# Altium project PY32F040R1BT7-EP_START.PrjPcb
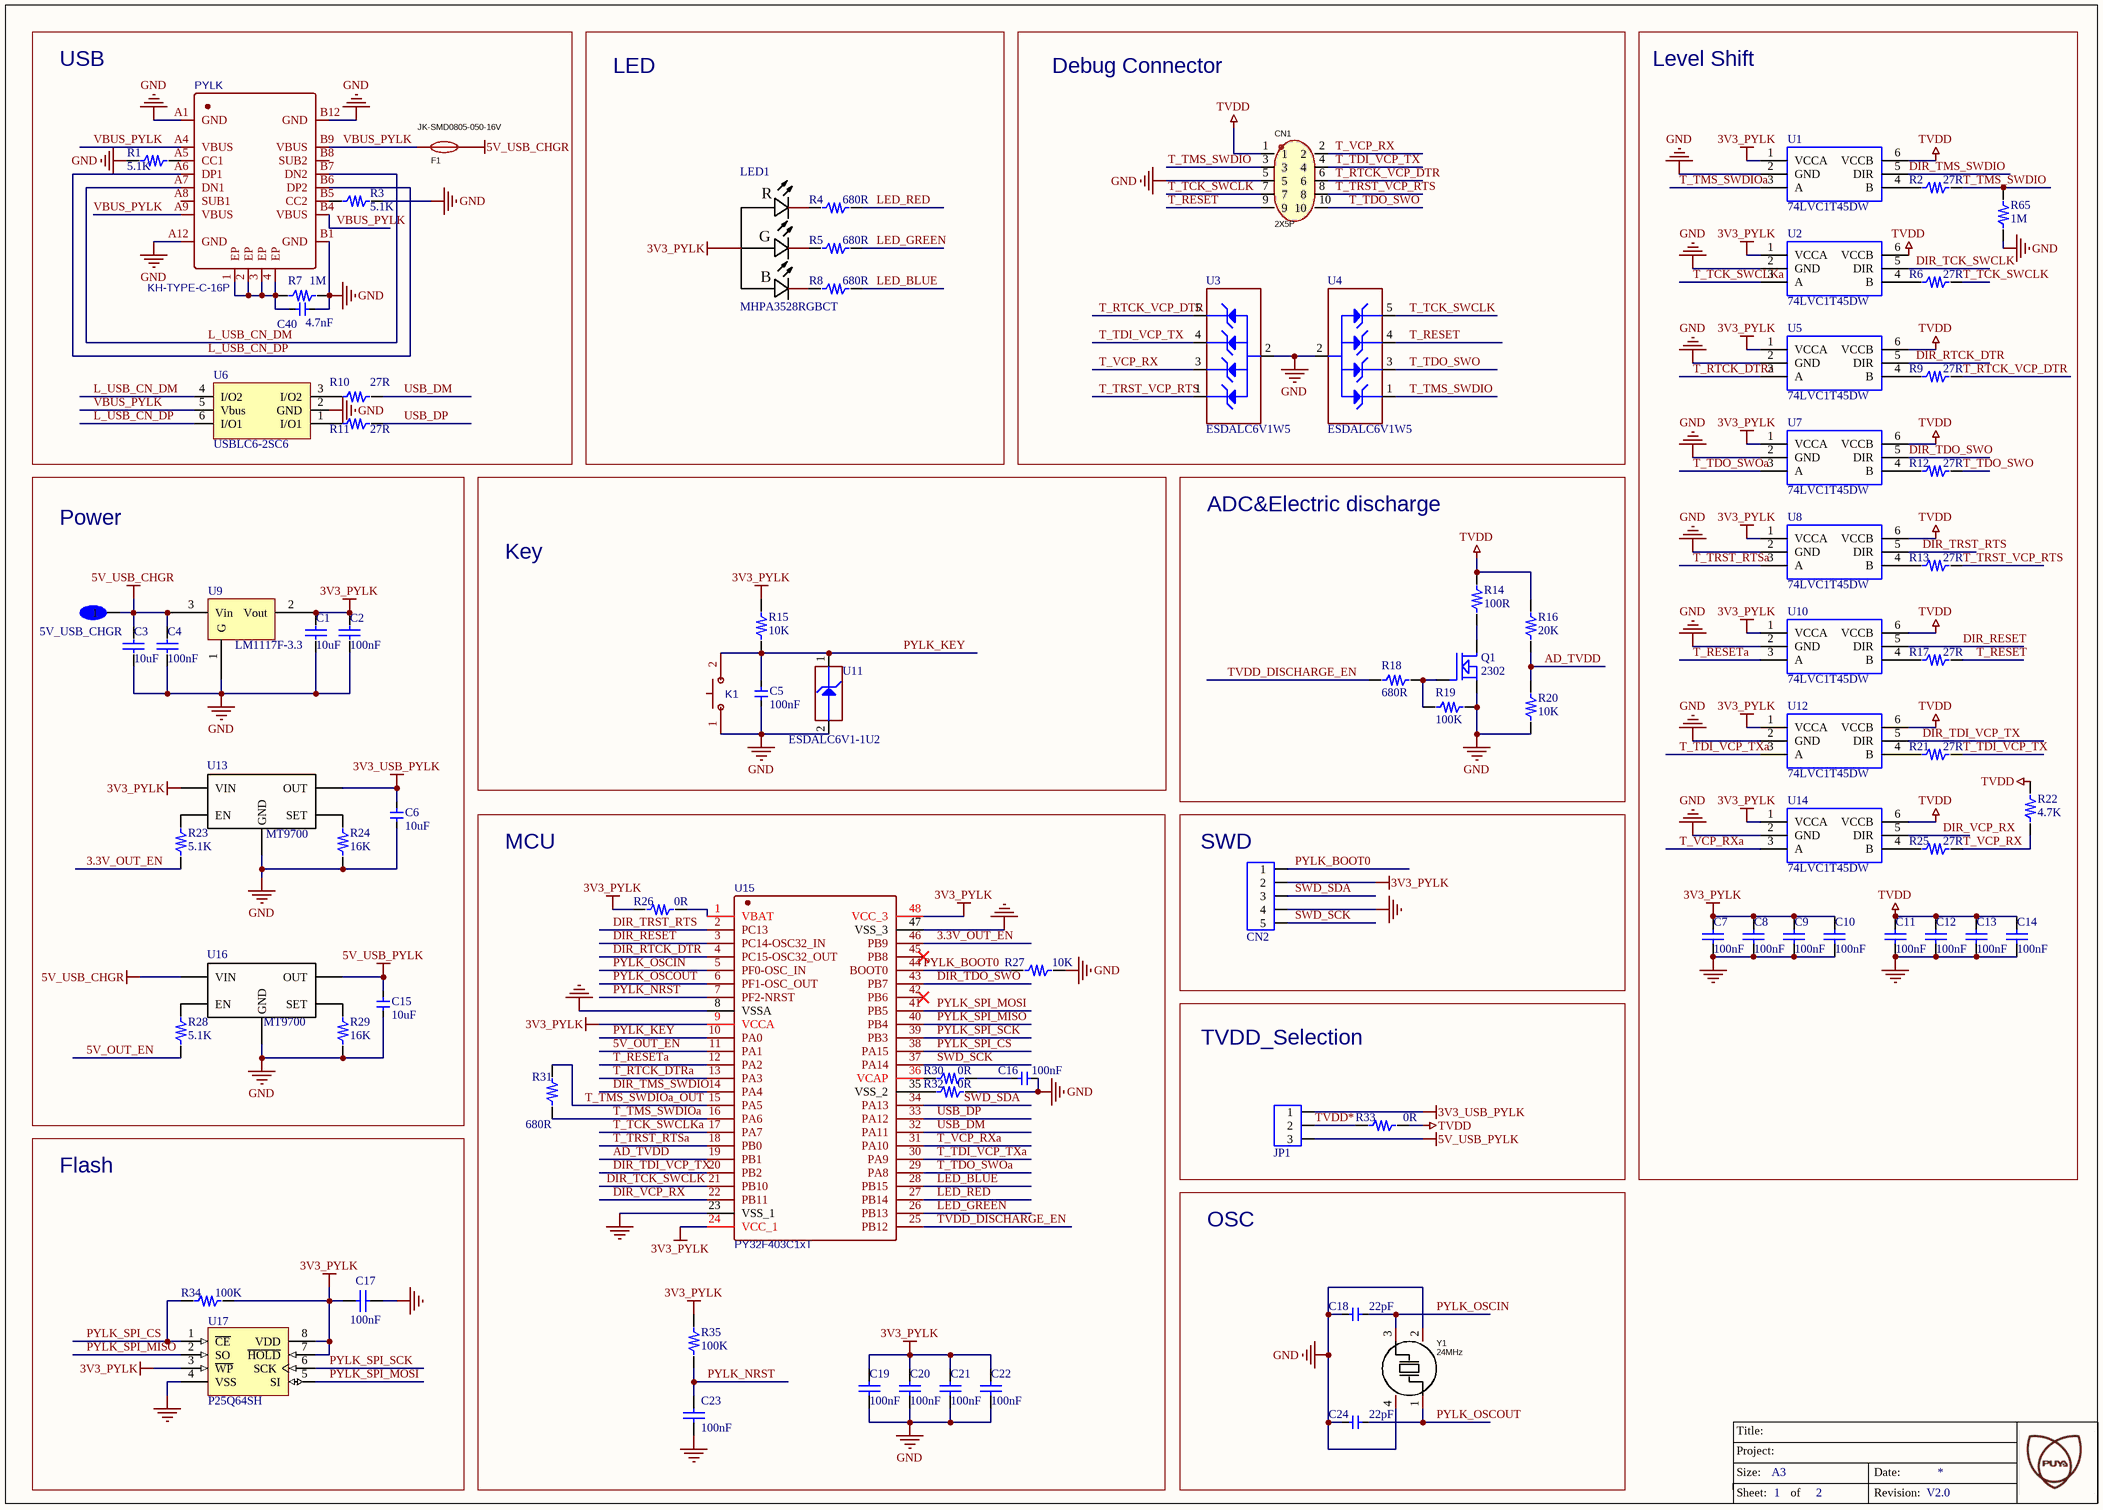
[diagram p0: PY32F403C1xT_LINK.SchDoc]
2 sheets, 157 parts. Net scope: global (net labels, ports and power ports of the same name join across sheets).
Board file: PY32F040R1BT7-EP_START.PcbDoc
Sheets:
  PY32F403C1xT_LINK.SchDoc
  PY32F040R1BT7-EP_START.SchDoc

## Sheet PY32F403C1xT_LINK.SchDoc: =DocumentName
size A3; Revision: V2.0; SheetNumber: 1; SheetTotal: 2; Project: PY32F040R1BT7-EP_START.PrjPcb

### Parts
5V_USB_CHGR  5V_USB_CHGR  [TP_SIN]
C1  10uF  [C0805]
C2  100nF  [C0603]
C3  10uF  [C0805]
C4  100nF  [C0603]
C5  100nF  [C0603]
C6  10uF  [C0805]
C7  100nF  [C0603]
C8  100nF  [C0603]
C9  100nF  [C0603]
C10  100nF  [C0603]
C11  100nF  [C0603]
C12  100nF  [C0603]
C13  100nF  [C0603]
C14  100nF  [C0603]
C15  10uF  [C0805]
C16  100nF  [C0603]
C17  100nF  [C0603]
C18  22pF  [C0603]
C19  100nF  [C0603]
C20  100nF  [C0603]
C21  100nF  [C0603]
C22  100nF  [C0603]
C23  100nF  [C0603]
C24  22pF  [C0603]
C40  4.7nF  [C0603]
CN1  2X5P  [HDR2X5]
CN2  CON5  [CON5]  (value not drawn)
F1  JK-SMD0805-050-16V  [F0805]
JP1  CON3  [CON3]  (value not drawn)
K1  TS-KG02S-AT43F  [Switch]  (value not drawn)
LED1  MHPA3528RGBCT  [LED-ARRAY-SMD_4P-L3.5-W2.8-TL]
PYLK  KH-TYPE-C-16P  [USB-C-SMD_KH-TYPE-C-16P]
Q1  2302  [SOT23]
R1  5.1K  [R0603]
R2  27R  [R0603]
R3  5.1K  [R0603]
R4  680R  [R0603]
R5  680R  [R0603]
R6  27R  [R0603]
R7  1M  [R0603]
R8  680R  [R0603]
R9  27R  [R0603]
R10  27R  [R0603]
R11  27R  [R0603]
R12  27R  [R0603]
R13  27R  [R0603]
R14  100R  [R0805]
R15  10K  [R0603]
R16  20K  [R0603]
R17  27R  [R0603]
R18  680R  [R0603]
R19  100K  [R0603]
R20  10K  [R0603]
R21  27R  [R0603]
R22  4.7K  [R0603]
R23  5.1K  [R0603]
R24  16K  [R0603]
R25  27R  [R0603]
R26  0R  [JP2_SMD]
R27  10K  [R0603]
R28  5.1K  [R0603]
R29  16K  [R0603]
R30  0R  [JP2_SMD]
R31  680R  [R0603]
R32  0R  [JP2_SMD]
R33  0R  [JP2_SMD]
R34  100K  [R0603]
R35  100K  [R0603]
R65  1M  [R0603]
U1  74LVC1T45DW  [SOT363]
U2  74LVC1T45DW  [SOT363]
U3  ESDALC6V1W5  [ESD_SOT323-5L]
U4  ESDALC6V1W5  [ESD_SOT323-5L]
U5  74LVC1T45DW  [SOT363]
U6  USBLC6-2SC6  [SOT23-6]
U7  74LVC1T45DW  [SOT363]
U8  74LVC1T45DW  [SOT363]
U9  LM1117F-3.3  [LM1117-3.3]
U10  74LVC1T45DW  [SOT363]
U11  value ESDALC6V1-1U2  [ESD_ST0201]  (hidden comment: ESD-TRANSIL)
U12  74LVC1T45DW  [SOT363]
U13  MT9700  [SOT23-5]
U14  74LVC1T45DW  [SOT363]
U15  PY32F403C1xT  [LQFP-48_L7.0-W7.0-P0.50-LS9.0-BL]
U16  MT9700  [SOT23-5]
U17  P25Q64SH  [SOP-8P]
Y1  24MHz  [CRYSTAL-SMD_4P-L3.2-W2.5-BL]

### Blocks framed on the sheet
USB: C40 F1 PYLK R1 R3 R7 R10 R11 U6
LED: LED1 R4 R5 R8
Debug Connector: CN1 U3 U4
Level Shift: C7-C14 R2 R6 R9 R12 R13 R17 R21 R22 R25 R65 U1 U2 U5 U7 U8 U10 U12 U14
Power: 5V_USB_CHGR C1-C4 C6 C15 R23 R24 R28 R29 U9 U13 U16
Key: C5 K1 R15 U11
ADC&Electric discharge: Q1 R14 R16 R18-R20
MCU: C16 C19-C23 R26 R27 R30-R32 R35 U15
SWD: CN2
TVDD_Selection: JP1 R33
Flash: C17 R34 U17
OSC: C18 C24 Y1

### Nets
3V3_PYLK: C1.2 C2.2 C7.2 C8.2 C9.2 C10.2 C17.2 C19.2 C20.2 C21.2 C22.2 CN2.2 LED1.1(-) R15.2 R26.1 R34.2 R35.2 U1.1(VCCA) U2.1(VCCA) U5.1(VCCA) U7.1(VCCA) U8.1(VCCA) U9.2(Vout) U10.1(VCCA) U12.1(VCCA) U13.5(VIN) U14.1(VCCA) U15.9(VCCA) U15.24(VCC_1) U15.48(VCC_3) U17.3(~{WP}) U17.7(~{HOLD}) U17.8(VDD)
3V3_USB_PYLK: C6.2 JP1.1 U13.1(OUT)
5V_USB_CHGR: 5V_USB_CHGR.1 C3.2 C4.2 F1.2 U9.3(Vin) U16.5(VIN)
5V_USB_PYLK: C15.2 JP1.3 U16.1(OUT)
GND: C1.1 C2.1 C3.1 C4.1 C5.1 C6.1 C7.1 C8.1 C9.1 C10.1 C11.1 C12.1 C13.1 C14.1 C15.1 C16.1 C17.1 C18.1 C19.1 C20.1 C21.1 C22.1 C23.1 C24.1 C40.1 CN1.5 CN2.4 K1.1(A) PYLK.A1(GND) PYLK.A12(GND) PYLK.B1(GND) PYLK.B12(GND) Q1.2(S) R1.1 R3.2 R7.2 R19.1 R20.1 R24.1 R27.2 R29.1 R32.2 R65.1 U1.2(GND) U2.2(GND) U3.2(GND) U4.2(GND) U5.2(GND) U6.2(GND) U7.2(GND) U8.2(GND) U9.1(G) U10.2(GND) U11.2(GND) U12.2(GND) U13.2(GND) U14.2(GND) U15.8(VSSA) U15.23(VSS_1) U15.47(VSS_3) U16.2(GND) U17.4(VSS) Y1.2(GND) Y1.4(GND)
TVDD: C11.2 C12.2 C13.2 C14.2 CN1.1 R14.2 R16.2 R22.2 R33.2 U1.6(VCCB) U2.6(VCCB) U5.6(VCCB) U7.6(VCCB) U8.6(VCCB) U10.6(VCCB) U12.6(VCCB) U14.6(VCCB)
3.3V_OUT_EN: R23.1 U15.46(PB9)
5V_OUT_EN: R28.1 U15.11(PA1)
AD_TVDD: R16.1 R20.2 U15.19(PB1)
DIR_RESET: U10.5(DIR) U15.3(PC14-OSC32_IN)
DIR_RTCK_DTR: U5.5(DIR) U15.4(PC15-OSC32_OUT)
DIR_TCK_SWCLK: U2.5(DIR) U15.21(PB10)
DIR_TDI_VCP_TX: U12.5(DIR) U15.20(PB2)
DIR_TDO_SWO: U7.5(DIR) U15.43(PB7)
DIR_TMS_SWDIO: U1.5(DIR) U15.14(PA4)
DIR_TRST_RTS: U8.5(DIR) U15.2(PC13)
DIR_VCP_RX: U14.5(DIR) U15.22(PB11)
L_USB_CN_DM: PYLK.A7(DN1) PYLK.B7(DN2) U6.4(I/O2)
L_USB_CN_DP: PYLK.A6(DP1) PYLK.B6(DP2) U6.6(I/O1)
LED_BLUE: R8.2 U15.28(PB15)
LED_GREEN: R5.2 U15.26(PB13)
LED_RED: R4.2 U15.27(PB14)
PYLK_BOOT0: CN2.1 R27.1 U15.44(BOOT0)
PYLK_KEY: C5.2 K1.2(B) R15.1 U11.1(IO1) U15.10(PA0)
PYLK_NRST: C23.2 R35.1 U15.7(PF2-NRST)
PYLK_OSCIN: C18.2 U15.5(PF0-OSC_IN) Y1.3(OSC2)
PYLK_OSCOUT: C24.2 U15.6(PF1-OSC_OUT) Y1.1(OSC1)
PYLK_SPI_CS: R34.1 U15.38(PA15) U17.1(~{CE})
PYLK_SPI_MISO: U15.40(PB4) U17.2(SO)
PYLK_SPI_MOSI: U15.41(PB5) U17.5(SI)
PYLK_SPI_SCK: U15.39(PB3) U17.6(SCK)
SWD_SCK: CN2.5 U15.37(PA14)
SWD_SDA: CN2.3 U15.34(PA13)
T_RESET: CN1.9 R17.2 U4.4(IO3)
T_RESETa: U10.3(A) U15.12(PA2)
T_RTCK_DTRa: U5.3(A) U15.13(PA3)
T_RTCK_VCP_DTR: CN1.6 R9.2 U3.5(IO4)
T_TCK_SWCLK: CN1.7 R6.2 U4.5(IO4)
T_TCK_SWCLKa: U2.3(A) U15.17(PA7)
T_TDI_VCP_TX: CN1.4 R21.2 U3.4(IO3)
T_TDI_VCP_TXa: U12.3(A) U15.30(PA9)
T_TDO_SWO: CN1.10 R12.2 U4.3(IO2)
T_TDO_SWOa: U7.3(A) U15.29(PA8)
T_TMS_SWDIO: CN1.3 R2.2 R65.2 U4.1(IO1)
T_TMS_SWDIOa: R31.1 U1.3(A) U15.16(PA6)
T_TMS_SWDIOa_OUT: R31.2 U15.15(PA5)
T_TRST_RTSa: U8.3(A) U15.18(PB0)
T_TRST_VCP_RTS: CN1.8 R13.2 U3.1(IO1)
T_VCP_RX: CN1.2 R22.1 R25.2 U3.3(IO2)
T_VCP_RXa: U14.3(A) U15.31(PA10)
TVDD*: JP1.2 R33.1
TVDD_DISCHARGE_EN: R18.2 U15.25(PB12)
USB_DM: R10.2 U15.32(PA11)
USB_DP: R11.2 U15.33(PA12)
VBUS_PYLK: F1.1 PYLK.A4(VBUS) PYLK.A9(VBUS) PYLK.B4(VBUS) PYLK.B9(VBUS) U6.5(Vbus)
NetC16_2: C16.2 R30.2
NetC40_2: C40.2 PYLK.1(EP) PYLK.2(EP) PYLK.3(EP) PYLK.4(EP) R7.1
NetLED1_2: LED1.2(-) R8.1
NetLED1_3: LED1.3(-) R5.1
NetLED1_4: LED1.4(-) R4.1
NetPYLK_A5: PYLK.A5(CC1) R1.2
NetPYLK_B5: PYLK.B5(CC2) R3.1
NetQ1_1: Q1.1(G) R18.1 R19.2
NetQ1_3: Q1.3(D) R14.1
NetR2_1: R2.1 U1.4(B)
NetR6_1: R6.1 U2.4(B)
NetR9_1: R9.1 U5.4(B)
NetR10_1: R10.1 U6.3(I/O2)
NetR11_1: R11.1 U6.1(I/O1)
NetR12_1: R12.1 U7.4(B)
NetR13_1: R13.1 U8.4(B)
NetR17_1: R17.1 U10.4(B)
NetR21_1: R21.1 U12.4(B)
NetR23_2: R23.2 U13.4(EN)
NetR24_2: R24.2 U13.3(SET)
NetR25_1: R25.1 U14.4(B)
NetR26_2: R26.2 U15.1(VBAT)
NetR28_2: R28.2 U16.4(EN)
NetR29_2: R29.2 U16.3(SET)
NetR30_1: R30.1 U15.36(VCAP)
NetR32_1: R32.1 U15.35(VSS_2)

Not connected (* = marked no-connect by the designer): PYLK A8(SUB1) B8(SUB2); U15 42(PB6)* 45(PB8)*

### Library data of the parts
5V_USB_CHGR = TP_SIN
C1 C3 C6 C15 = C0805: PCB DECAL: 0805
C2 C4 C5 C16 C18 C24 C40 = C0603: PCB DECAL: 0603
C7-C14 C17 C19-C23 = 贴片高压陶瓷电容: Capacitor (Semiconductor SIM Model); 器件封装(外观): 0603; Value: 104
CN1 = 2X5P: Manufacturer: XFCN(兴飞); Symbol: PZ254V-12-10P; Add into BOM: yes; Pitch: 2.54mm; Circluar Pins/Square Pins: 方针
F1 = JK-SMD0805-050-16V: Manufacturer: JK(金科); Add into BOM: yes; Voltage - Max: 6V; Current - Max: 100A; Hold Current: 500mA; Trip Current: 1A; Power Dissipation: 600mW; Resistance - Initial (Ri) (Min): 150mΩ; Resistance - Post Trip (R1) (Max): 850mΩ; Time to Trip(Max): 100ms
K1 = 1TS002B-2600-5001_key: BOM_Manufacturer: HYP; Contributor: LCSC
LED1 = MHPA3528RGBCT: Manufacturer: MEIHUA(美华); Add into BOM: yes
PYLK = KH-TYPE-C-16P: BOM_Manufacturer: Shenzhen Kinghelm Elec; Contributor: LCSC
Q1 = MOSFET N: Value: SI2302
R1-R13 R15-R35 R65 = R0603: PCB DECAL: 0603
R14 = R0805: PCB DECAL: 0805
U3 U4 = ESDALC6V1W5: Dual Transil array for ESD protection; Internal_Part_Number: MCD-00136; Part_Type: Diode; Manufacturer: STMICROELECTRONICS; ECCN_US: EAR99; ECCN_EU: NEC; Provided_By: Subcon; Initial_Board_Reference: MB1262
U6 = USBLC6-2SC6: Function: ESD EMI fliter
U9 = LM1117-3.3
U11 = ESD-TRANSIL: ESD protection 6V1; Internal_Part_Number: MCD-00170; Part_Type: Diode; Manufacturer: STMICROELECTRONICS; ECCN_US: EAR99; ECCN_EU: NEC; Provided_By: Subcon; Initial_Board_Reference: MB1274
U15 = PY32F403C1xT: LQFP48; BOM_Manufacturer: PUYA(普冉)
U17 = SST25VF010: Value: SST25VF020B; 器件封装(外观): SOP8
Y1 = ABM8AIG-24.000MHZ-82Z-T: ±20ppm , 12.5pF , T_use: -40°C~125°C; Manufacturer: ABRACON; Add into BOM: yes; External load capacitor: 8pF; Frequency Stability(Full temperature range): ±50ppm; Equivalent Series Resistance (ESR): 50Ω

## Sheet PY32F040R1BT7-EP_START.SchDoc: =DocumentName
size A3; Revision: V2.0; SheetNumber: 2; SheetTotal: 2; Project: PY32F040R1BT7-EP_START.PrjPcb
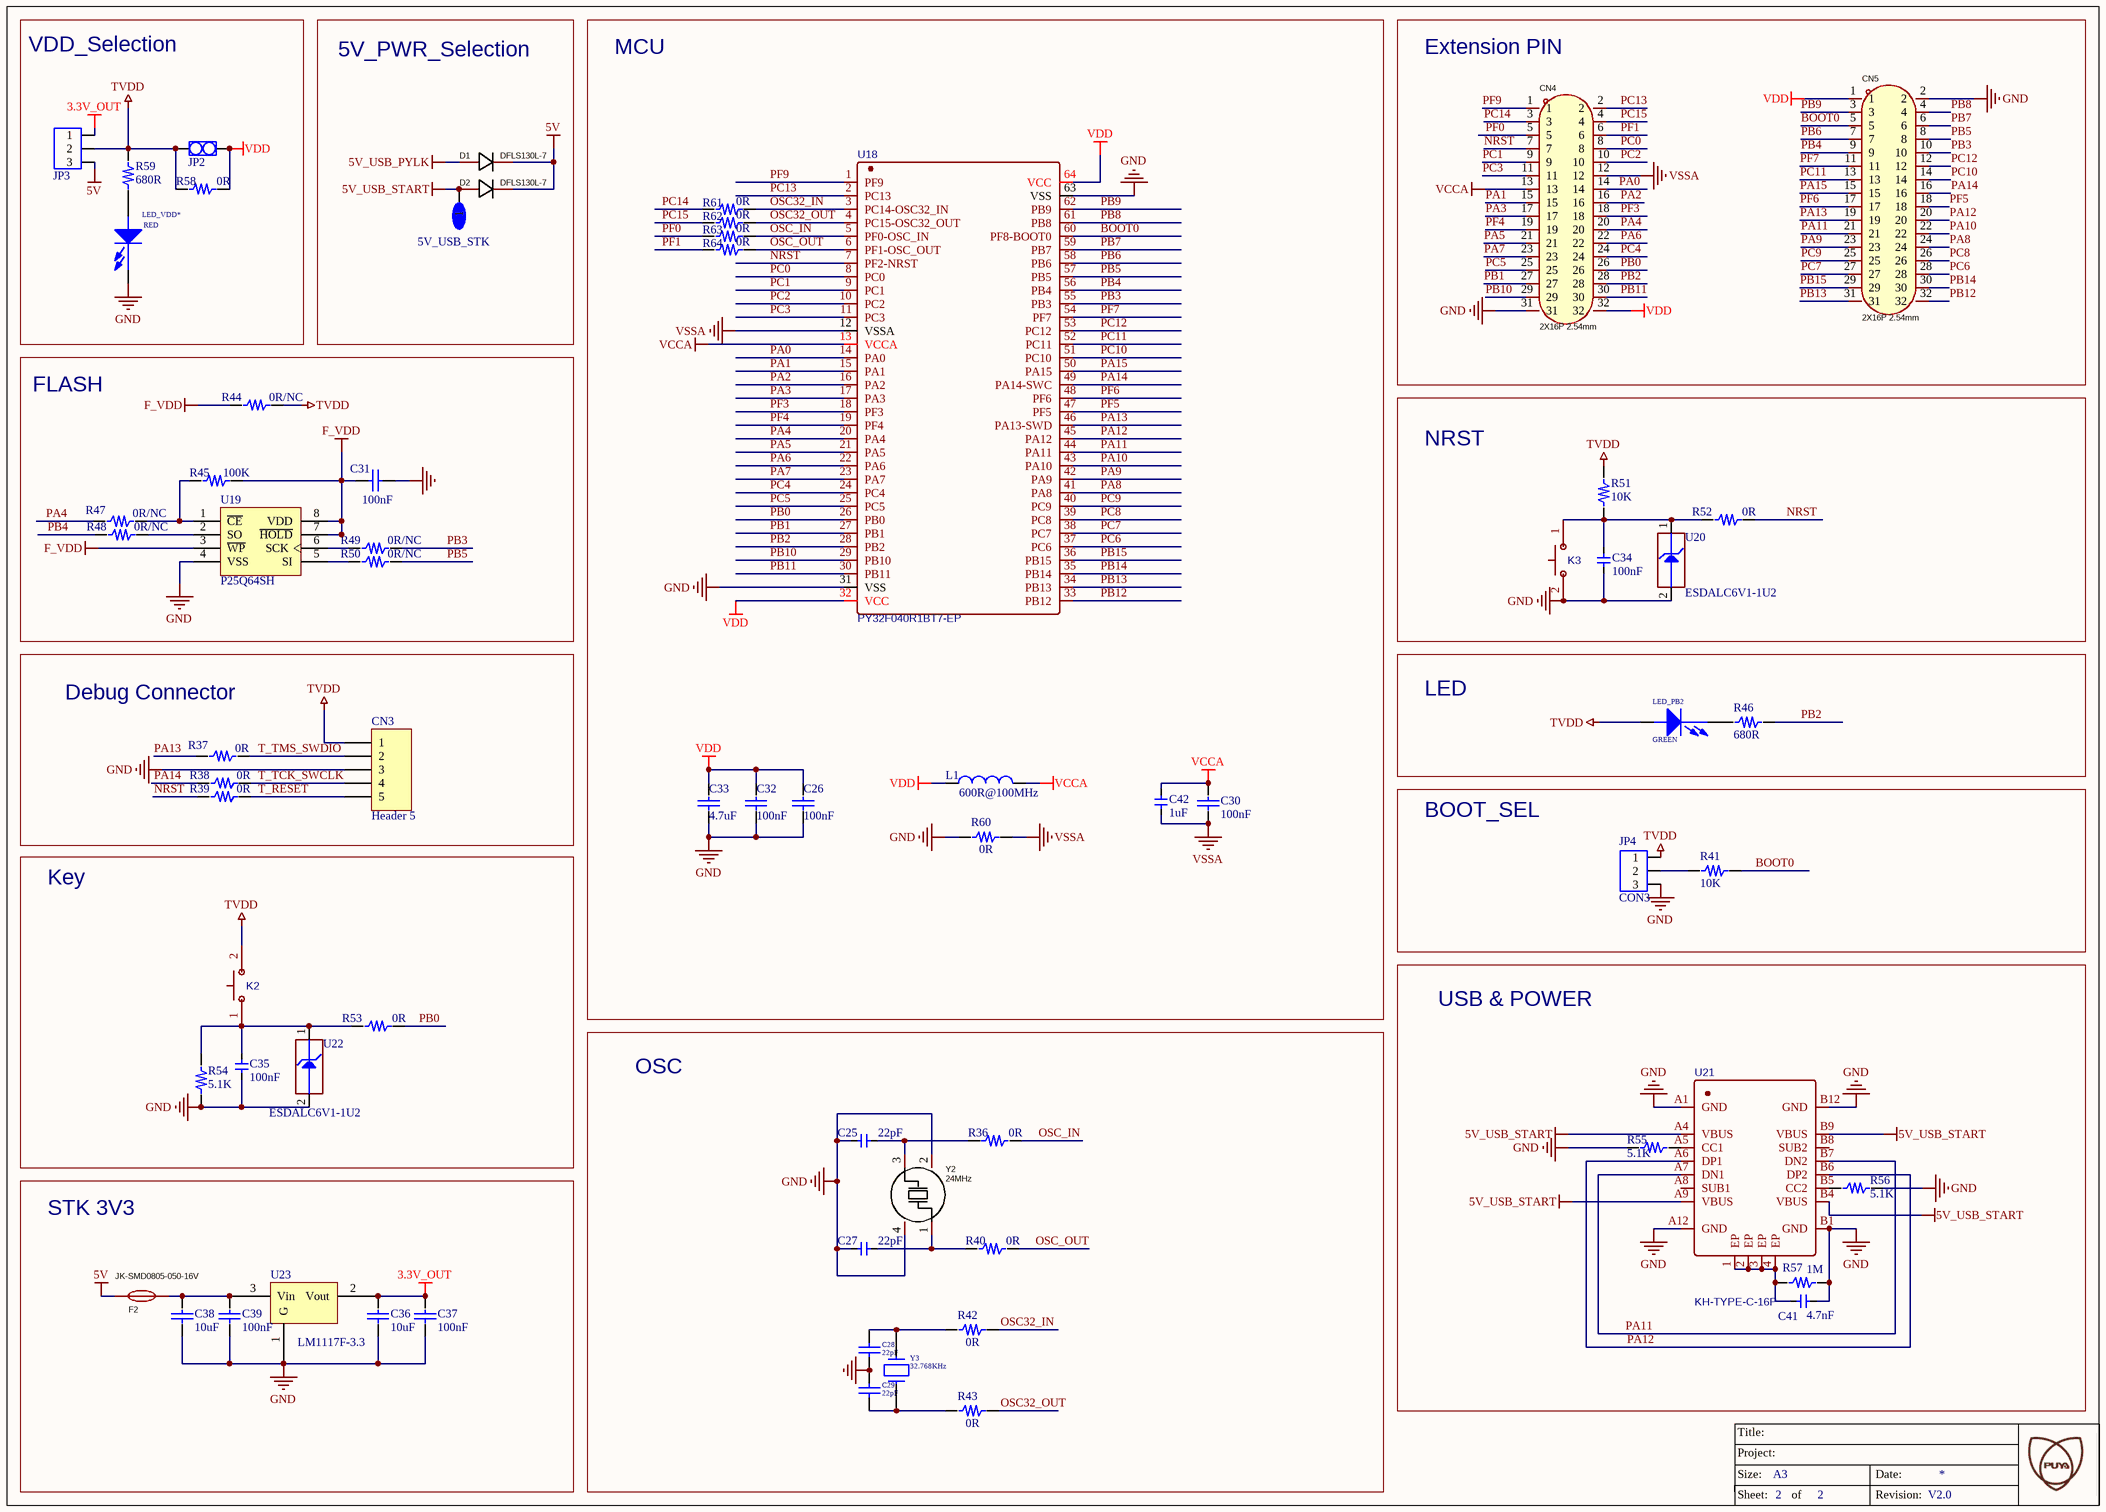
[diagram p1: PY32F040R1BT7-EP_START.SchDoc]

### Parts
5V_USB_STK  5V_USB_STK  [TP_SIN]
C25  22pF  [C0603]
C26  100nF  [C0603]
C27  22pF  [C0603]
C28  22pF  [0603C]
C29  22pF  [0603C]
C30  100nF  [C0603]
C31  100nF  [C0603]
C32  100nF  [C0603]
C33  4.7uF  [C0603]
C34  100nF  [C0603]
C35  100nF  [C0603]
C36  10uF  [C0805]
C37  100nF  [C0603]
C38  10uF  [C0805]
C39  100nF  [C0603]
C41  4.7nF  [C0603]
C42  1uF  [C0603]
CN3  Header 5  [HDR1X5]
CN4  2X16P 2.54mm  [HDR-TH_32P-P2.54-V-M-R2-C16-S2.54-3]
CN5  2X16P 2.54mm  [HDR-TH_32P-P2.54-V-M-R2-C16-S2.54-3]
D1  DFLS130L-7  [POWERDI-123_L2.8-W1.8-LS3.7-RD]
D2  DFLS130L-7  [POWERDI-123_L2.8-W1.8-LS3.7-RD]
F2  JK-SMD0805-050-16V  [F0805]
JP2  CON2  [CON2]  (value not drawn)
JP3  CON3  [CON3]  (value not drawn)
JP4  CON3  [CON3]
K2  TS-KG02S-AT43F  [Switch]  (value not drawn)
K3  TS-KG02S-AT43F  [Switch]  (value not drawn)
L1  value 600R@100MHz  [L0603]  (hidden comment: BEAD)
LED_PB2  GREEN  [0603_LED]
LED_VDD*  RED  [0603_LED]
R36  0R  [JP2_SMD]
R37  0R  [JP2_SMD]
R38  0R  [JP2_SMD]
R39  0R  [JP2_SMD]
R40  0R  [JP2_SMD]
R41  10K  [R0603]
R42  0R  [JP2_SMD]
R43  0R  [JP2_SMD]
R44  0R/NC  [JP2_SMD]
R45  100K  [R0603]
R46  680R  [R0603]
R47  0R/NC  [JP2_SMD]
R48  0R/NC  [JP2_SMD]
R49  0R/NC  [JP2_SMD]
R50  0R/NC  [JP2_SMD]
R51  10K  [R0603]
R52  0R  [JP2_SMD]
R53  0R  [JP2_SMD]
R54  5.1K  [R0603]
R55  5.1K  [R0603]
R56  5.1K  [R0603]
R57  1M  [R0603]
R58  0R  [JP2_SMD]
R59  680R  [R0603]
R60  0R  [JP2_SMD]
R61  0R  [JP2_SMD]
R62  0R  [JP2_SMD]
R63  0R  [JP2_SMD]
R64  0R  [JP2_SMD]
U18  PY32F040R1BT7-EP  [LQFP-64_L12.0-W12.0-P0.50-LS12.0-BL]
U19  P25Q64SH  [SOP-8P]
U20  value ESDALC6V1-1U2  [ESD_ST0201]  (hidden comment: ESD-TRANSIL)
U21  KH-TYPE-C-16P  [USB-C-SMD_KH-TYPE-C-16P]
U22  value ESDALC6V1-1U2  [ESD_ST0201]  (hidden comment: ESD-TRANSIL)
U23  LM1117F-3.3  [LM1117-3.3]
Y2  24MHz  [CRYSTAL-SMD_4P-L3.2-W2.5-BL]
Y3  32.768KHz  [CRYSTAL-SMD_L3.2-W1.5-1]

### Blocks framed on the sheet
VDD_Selection: JP2 JP3 LED_VDD* R58 R59
5V_PWR_Selection: 5V_USB_STK D1 D2
MCU: C26 C30 C32 C33 C42 L1 R60-R64 U18
Extension PIN: CN4 CN5
FLASH: C31 R44 R45 R47-R50 U19
NRST: C34 K3 R51 R52 U20
Debug Connector: CN3 R37-R39
LED: LED_PB2 R46
BOOT_SEL: JP4 R41
Key: C35 K2 R53 R54 U22
USB & POWER: C41 R55-R57 U21
OSC: C25 C27-C29 R36 R40 R42 R43 Y2 Y3
STK 3V3: C36-C39 F2 U23

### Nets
3.3V_OUT: C36.2 C37.2 JP3.1 U23.2(Vout)
5V: D1.1 D2.1 F2.1 JP3.3
5V_USB_PYLK: D1.2
5V_USB_START: 5V_USB_STK.1 D2.2 U21.A4(VBUS) U21.A9(VBUS) U21.B4(VBUS) U21.B9(VBUS)
F_VDD: C31.2 R44.2 R45.2 U19.3(~{WP}) U19.7(~{HOLD}) U19.8(VDD)
GND: C25.1 C26.2 C27.1 C28.2 C29.1 C31.1 C32.1 C33.1 C34.1 C35.1 C36.1 C37.1 C38.1 C39.1 C41.1 CN3.3 CN4.31 CN5.2 JP4.3 K3.2(B) LED_VDD*.2(CATHODE) R54.1 R55.2 R56.1 R57.1 R60.2 U18.31(VSS) U18.63(VSS) U19.4(VSS) U20.2(GND) U21.A1(GND) U21.A12(GND) U21.B1(GND) U21.B12(GND) U22.2(GND) U23.1(G) Y2.2(GND) Y2.4(GND)
TVDD: CN3.1 JP2.1 JP3.2 JP4.1 K2.2(B) LED_PB2.1(ANODE) R44.1 R51.1 R58.1 R59.2
VCCA: C30.2 C42.1 CN4.13 L1.2 U18.13(VCCA)
VDD: C26.1 C32.2 C33.2 CN4.32 CN5.1 JP2.2 L1.1 R58.2 U18.32(VCC) U18.64(VCC)
VSSA: C30.1 C42.2 CN4.12 R60.1 U18.12(VSSA)
BOOT0: CN5.5 R41.2 U18.60(PF8-BOOT0)
NRST: CN4.7 R39.2 R52.2 U18.7(PF2-NRST)
OSC32_IN: R42.1 R61.1 U18.3(PC14-OSC32_IN)
OSC32_OUT: R43.1 R62.1 U18.4(PC15-OSC32_OUT)
OSC_IN: R36.2 R63.1 U18.5(PF0-OSC_IN)
OSC_OUT: R40.2 R64.1 U18.6(PF1-OSC_OUT)
PA0: CN4.14 U18.14(PA0)
PA1: CN4.15 U18.15(PA1)
PA2: CN4.16 U18.16(PA2)
PA3: CN4.17 U18.17(PA3)
PA4: CN4.20 R47.2 U18.20(PA4)
PA5: CN4.21 U18.21(PA5)
PA6: CN4.22 U18.22(PA6)
PA7: CN4.23 U18.23(PA7)
PA8: CN5.24 U18.41(PA8)
PA9: CN5.23 U18.42(PA9)
PA10: CN5.22 U18.43(PA10)
PA11: CN5.21 U18.44(PA11) U21.A7(DN1) U21.B7(DN2)
PA12: CN5.20 U18.45(PA12) U21.A6(DP1) U21.B6(DP2)
PA13: CN5.19 R37.2 U18.46(PA13-SWD)
PA14: CN5.16 R38.2 U18.49(PA14-SWC)
PA15: CN5.15 U18.50(PA15)
PB0: CN4.26 R53.2 U18.26(PB0)
PB1: CN4.27 U18.27(PB1)
PB2: CN4.28 R46.2 U18.28(PB2)
PB3: CN5.10 R49.1 U18.55(PB3)
PB4: CN5.9 R48.2 U18.56(PB4)
PB5: CN5.8 R50.1 U18.57(PB5)
PB6: CN5.7 U18.58(PB6)
PB7: CN5.6 U18.59(PB7)
PB8: CN5.4 U18.61(PB8)
PB9: CN5.3 U18.62(PB9)
PB10: CN4.29 U18.29(PB10)
PB11: CN4.30 U18.30(PB11)
PB12: CN5.32 U18.33(PB12)
PB13: CN5.31 U18.34(PB13)
PB14: CN5.30 U18.35(PB14)
PB15: CN5.29 U18.36(PB15)
PC0: CN4.8 U18.8(PC0)
PC1: CN4.9 U18.9(PC1)
PC2: CN4.10 U18.10(PC2)
PC3: CN4.11 U18.11(PC3)
PC4: CN4.24 U18.24(PC4)
PC5: CN4.25 U18.25(PC5)
PC6: CN5.28 U18.37(PC6)
PC7: CN5.27 U18.38(PC7)
PC8: CN5.26 U18.39(PC8)
PC9: CN5.25 U18.40(PC9)
PC10: CN5.14 U18.51(PC10)
PC11: CN5.13 U18.52(PC11)
PC12: CN5.12 U18.53(PC12)
PC13: CN4.2 U18.2(PC13)
PC14: CN4.3 R61.2
PC15: CN4.4 R62.2
PF0: CN4.5 R63.2
PF1: CN4.6 R64.2
PF3: CN4.18 U18.18(PF3)
PF4: CN4.19 U18.19(PF4)
PF5: CN5.18 U18.47(PF5)
PF6: CN5.17 U18.48(PF6)
PF7: CN5.11 U18.54(PF7)
PF9: CN4.1 U18.1(PF9)
T_RESET: CN3.5 R39.1
T_TCK_SWCLK: CN3.4 R38.1
T_TMS_SWDIO: CN3.2 R37.1
NetC25_2: C25.2 R36.1 Y2.3(OSC2)
NetC27_2: C27.2 R40.1 Y2.1(OSC1)
NetC28_1: C28.1 R42.2 Y3.2
NetC29_2: C29.2 R43.2 Y3.1
NetC34_2: C34.2 K3.1(A) R51.2 R52.1 U20.1(IO1)
NetC35_2: C35.2 K2.1(A) R53.1 R54.2 U22.1(IO1)
NetC38_2: C38.2 C39.2 F2.2 U23.3(Vin)
NetC41_2: C41.2 R57.2 U21.1(EP) U21.2(EP) U21.3(EP) U21.4(EP)
NetJP4_2: JP4.2 R41.1
NetLED_PB2_2: LED_PB2.2(CATHODE) R46.1
NetLED_VDD*_1: LED_VDD*.1(ANODE) R59.1
NetR45_1: R45.1 R47.1 U19.1(~{CE})
NetR48_1: R48.1 U19.2(SO)
NetR49_2: R49.2 U19.6(SCK)
NetR50_2: R50.2 U19.5(SI)
NetR55_1: R55.1 U21.A5(CC1)
NetR56_2: R56.2 U21.B5(CC2)

Not connected (* = marked no-connect by the designer): U21 A8(SUB1) B8(SUB2)

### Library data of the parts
5V_USB_STK = TP_SIN
C25-C27 C30 C32-C35 C37 C39 C41 C42 = C0603: PCB DECAL: 0603
C28 C29 = Cap: Capacitor
C31 = 贴片高压陶瓷电容: as C7 on sheet PY32F403C1xT_LINK
C36 C38 = C0805: PCB DECAL: 0805
CN3 = Header 5: Header, 5-Pin
CN4 CN5 = 2X16P 2.54mm: Manufacturer: XKB Connection(中国星坤); Symbol: X6522WV-2X16H-C60D30-E80; Add into BOM: yes; Circluar Pins/Square Pins: 方针; Current Rating (Max): 3A; Voltage Rating (Max): 250V; Soldering Temperature(Max): 260℃
D1 D2 = DFLS130L-7: Manufacturer: DIODES(美台); Add into BOM: yes; Forward Voltage (Vf@If): 310mV@1A; Reverse Voltage (Vr): 30V; Average Rectified Current (Io): 1A
F2 = JK-SMD0805-050-16V: as F1 on sheet PY32F403C1xT_LINK
JP2 = CON2_DIP
JP3 = JP3
K2 K3 = 1TS002B-2600-5001_key: BOM_Manufacturer: HYP; Contributor: LCSC
L1 = BEAD: SMD Chip ferrite bead, 600R@100MHz +/-25%, 350mA, 500mohm DC, 0603, T=0.8mm; Internal_Part_Number: MCD-00047; Part_Type: Inductor; Manufacturer_Part_Number: FCM1608KF-601T03; Manufacturer: TAI-TECH; Provided_By: SUBCO
LED_PB2 LED_VDD* = PDI-E803_Dup1
R36-R64 = R0603: PCB DECAL: 0603
U18 = PY32F040R1BT7-EP: LQFP64; BOM_Manufacturer: PUYA(普冉)
U19 = SST25VF010: Value: SST25VF020B; 器件封装(外观): SOP8
U20 U22 = ESD-TRANSIL: as U11 on sheet PY32F403C1xT_LINK
U21 = KH-TYPE-C-16P: as PYLK on sheet PY32F403C1xT_LINK
U23 = LM1117-3.3
Y2 = ABM8AIG-24.000MHZ-82Z-T: as Y1 on sheet PY32F403C1xT_LINK
Y3 = CRYSTAL_1: Crystal; Value: X503225MSB2GI

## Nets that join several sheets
5V_USB_PYLK: PY32F403C1xT_LINK (C15.2 JP1.3 U16.1), PY32F040R1BT7-EP_START (D1.2)
GND: PY32F403C1xT_LINK (64 pins), PY32F040R1BT7-EP_START (38 pins)
TVDD: PY32F403C1xT_LINK (17 pins), PY32F040R1BT7-EP_START (10 pins)
T_RESET: PY32F403C1xT_LINK (CN1.9 R17.2 U4.4), PY32F040R1BT7-EP_START (CN3.5 R39.1)
T_TCK_SWCLK: PY32F403C1xT_LINK (CN1.7 R6.2 U4.5), PY32F040R1BT7-EP_START (CN3.4 R38.1)
T_TMS_SWDIO: PY32F403C1xT_LINK (CN1.3 R2.2 R65.2 U4.1), PY32F040R1BT7-EP_START (CN3.2 R37.1)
